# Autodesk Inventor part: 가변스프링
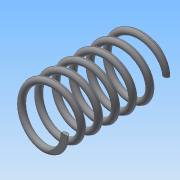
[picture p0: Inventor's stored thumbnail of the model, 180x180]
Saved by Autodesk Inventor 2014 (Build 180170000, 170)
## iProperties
Created: 2018-07
Part Number: 가변스프링
Material: 일반
Document SubType Name: Modeling
Designer: SEO-12
Density: 1 g/cm^3
Appearance: 기본값
Mass: 0.934904 g
Surface Area: 18.9531 cm^2
Volume: 0.934904 cm^3
Author: SEO-12
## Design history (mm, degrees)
sketch "스케치1"
  geometry: L1 (0, 32.152)-(33.453, 32.152); L2 (8, 0)-(0, 0); L3 (0, 0)-(0, 32.152); C1 r 1 at (8, 0); 1 further point
  constraints: 6 end point, 2 coincident, 1 centre point, 1 horizontal, 1 parallel, 1 vertical
  dimensions: "d0" = 2 diameter of C1; "d1" = 16 diameter of C1.centre L3; "d2" = 32.15161 distance between parallel lines of L2 L1 (derived)
feature "코일1" sketch "스케치1" pitch "d3" = 10; turns "d5" = 6; dims "d4" = 32.15161 (= d2), "d6" = 0, angle "d7" = 90 deg, angle "d8" = 90 deg, "d9" = 0, "d10" = 0
sketch "스케치2"
  geometry: L1 (32.152, 16.622)-(0, 16.622); L2 (0, 16.622)-(0, -16.622); L3 (0, -16.622)-(32.152, -16.622); L4 (32.152, -16.622)-(32.152, 16.622); 2 further points
  constraints: 8 end point, 2 parallel, 1 coincident, 1 horizontal, 1 midpoint, 1 perpendicular
  dimensions: "d11" = 32.15161 distance between parallel lines of L2 L4 (derived)
extrude "돌출1" sketch "스케치2" stored distance "d12" = 10; taper "d13" = 0 deg
node "솔리드1"
